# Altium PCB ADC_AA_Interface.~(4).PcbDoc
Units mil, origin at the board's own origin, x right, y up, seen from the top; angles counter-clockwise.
Board outline 2600 x 10000 mil, 6 copper layers (Top Layer, InternalPlane1, MidLayer1, InternalPlane2, InternalPlane3, Bottom Layer); 10 components, 66 nets, 277 pads, 10 vias.
Unrouted connection lines stored in the file: 1.
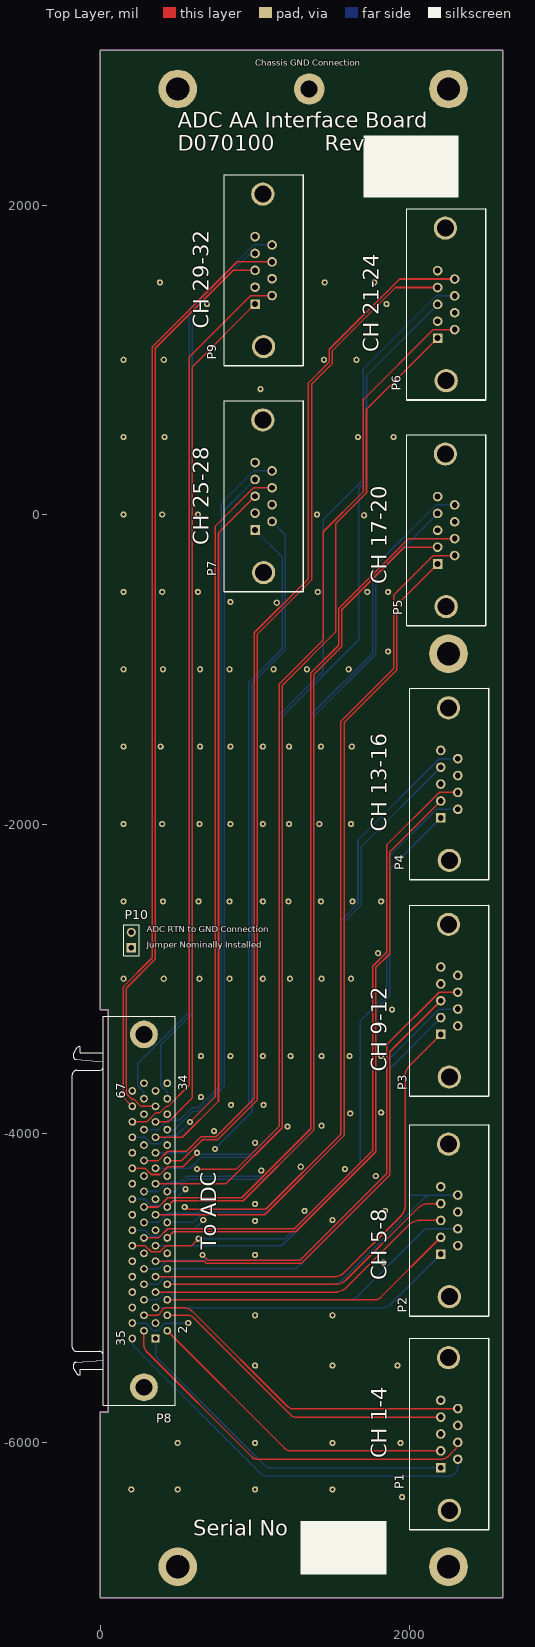
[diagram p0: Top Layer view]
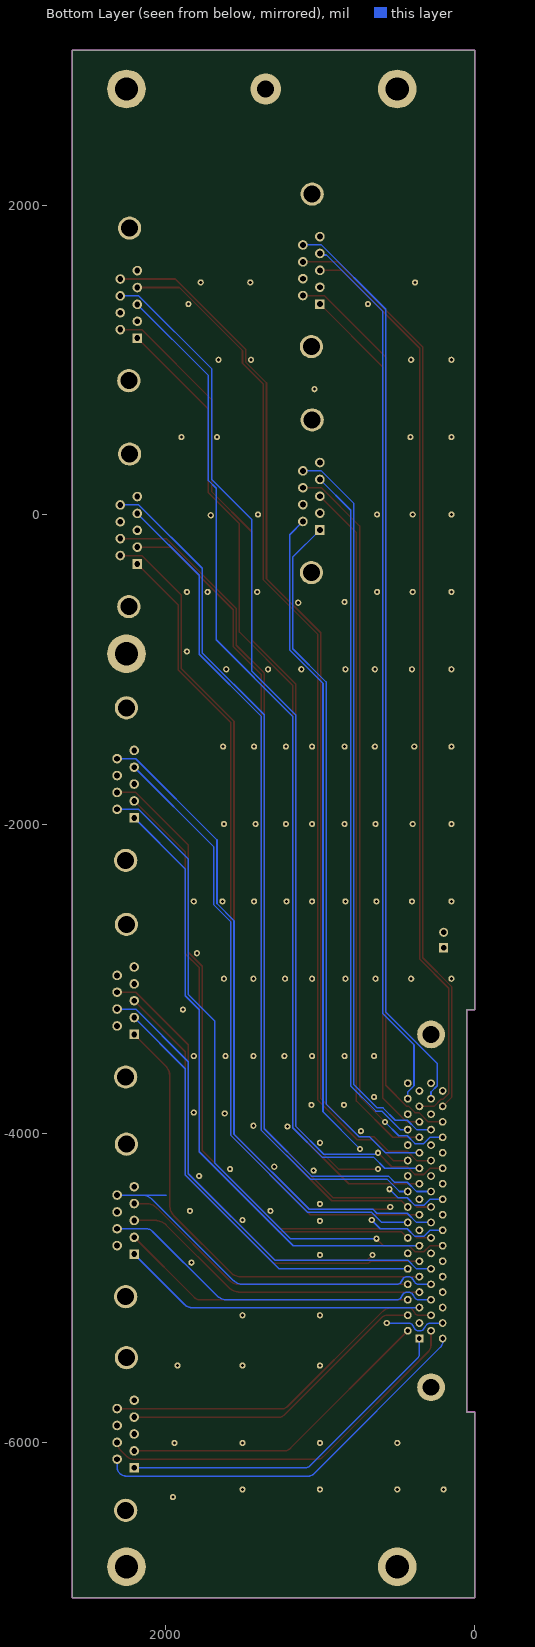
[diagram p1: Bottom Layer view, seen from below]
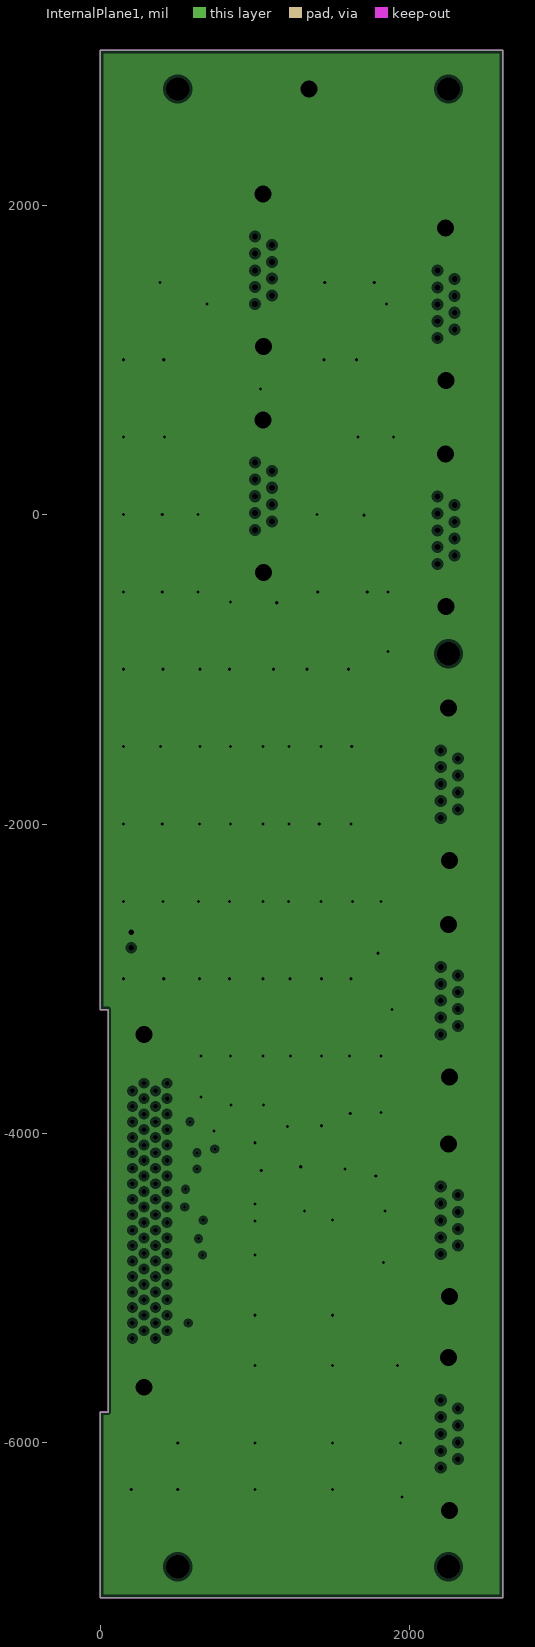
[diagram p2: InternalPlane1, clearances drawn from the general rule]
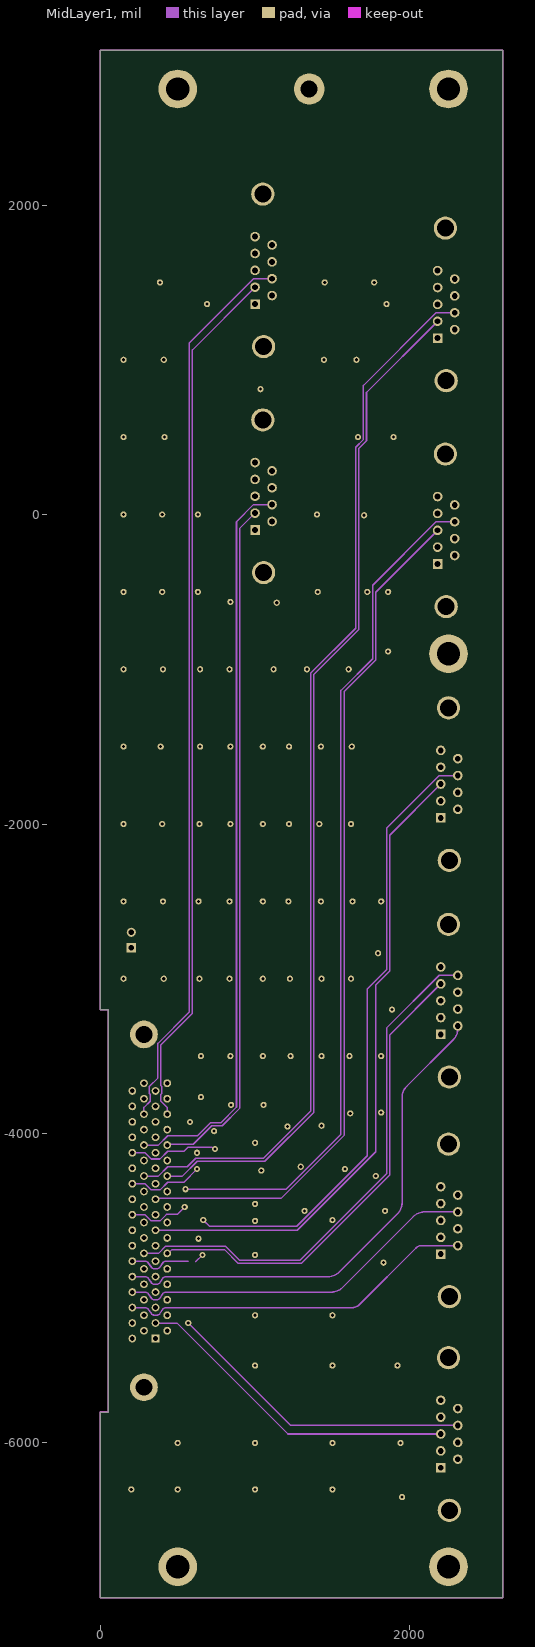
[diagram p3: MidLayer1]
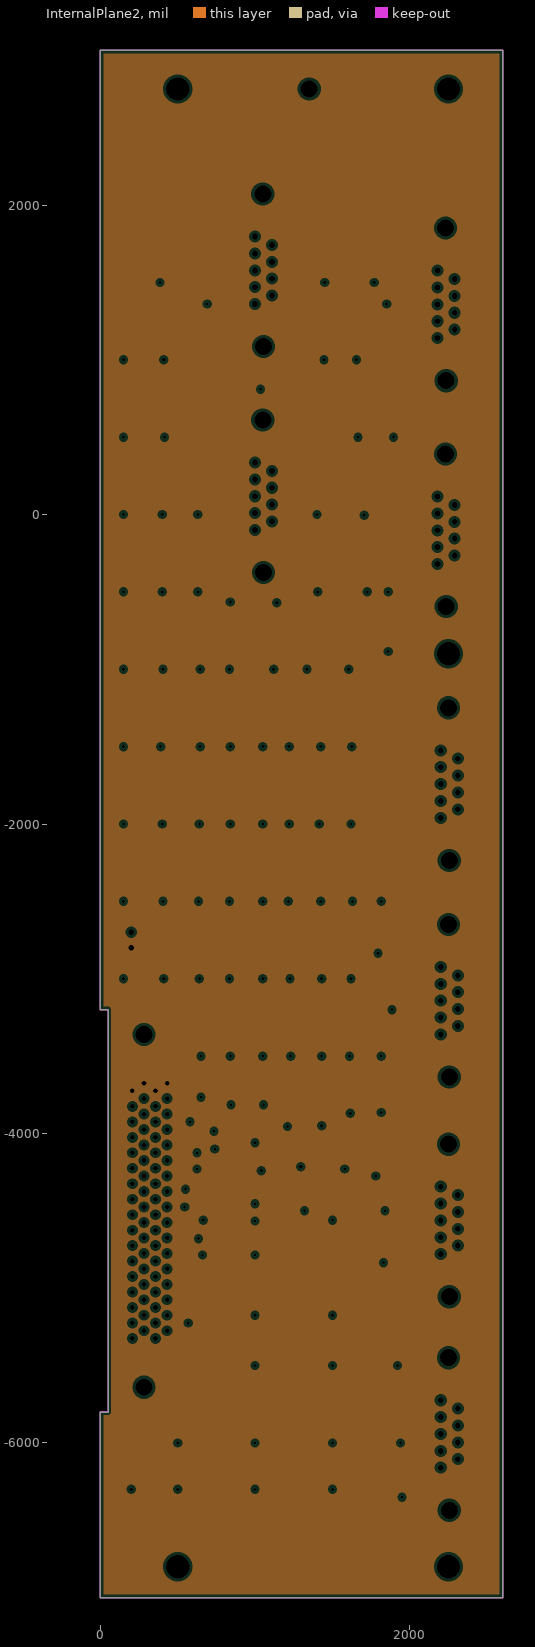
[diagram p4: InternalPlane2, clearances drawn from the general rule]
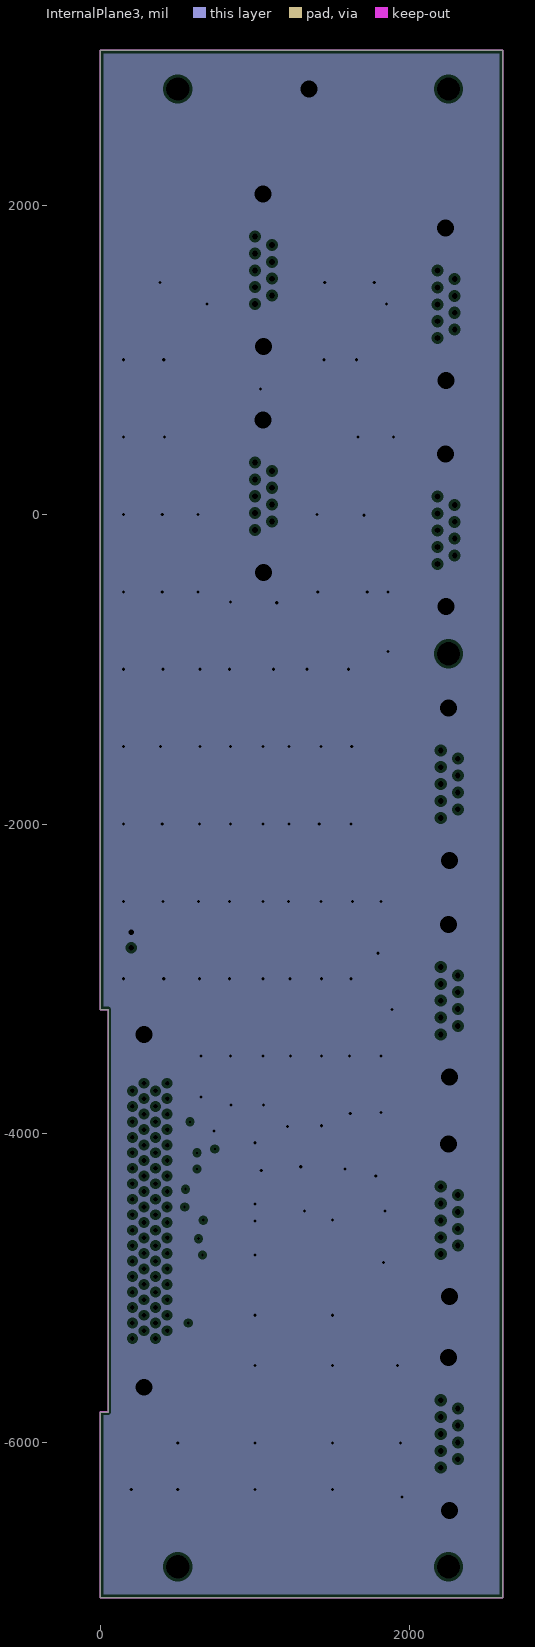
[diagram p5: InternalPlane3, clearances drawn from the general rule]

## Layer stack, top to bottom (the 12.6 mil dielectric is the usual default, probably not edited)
Top Solder: solder mask 0.4, Solder Resist, Dk 3.5
Top Layer: signal copper 1.4
Dielectric1: core 12.6, FR-4, Dk 4.8
InternalPlane1: plane copper 1.4, net GND
Dielectric3: prepreg 12.6, FR-4, Dk 4.8
MidLayer1: signal copper 1.4
Dielectric2: core 12.6, FR-4, Dk 4.8
InternalPlane2: plane copper 1.4, net RTN
Dielectric4: prepreg 12.6, FR-4, Dk 4.8
InternalPlane3: plane copper 1.4, net GND
Dielectric5: core 12.6, FR-4, Dk 4.8
Bottom Layer: signal copper 1.4
Bottom Solder: solder mask 0.4, Solder Resist, Dk 3.5

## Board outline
0,-7000 0,-5800 50,-5800 50,-3200 0,-3200 0,3000 2600,3000 2600,-7000

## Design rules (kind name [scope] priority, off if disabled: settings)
Clearance [All] p1: gap=10 ignorepadtopadclearanceinfootprint=FALSE except(0: Arc-Hole Track-Hole SMDPad-Hole THPad-Hole Via-Hole Fill-Hole Poly-Hole Region-Hole Text-Hole)
FabricationTestPointUsage TestPointUsage [All] p1: valid=0 allowmultiple=FALSE
FabricationTestpoint Testpoint [All] p1: side=3 testpointundercomponent=TRUE minsize=40 maxsize=100 preferedsize=60 minholesize=0 maxholesize=40 preferedholesize=32 testpointgrid=1 allowsidetop=TRUE allowsidebottom=TRUE usegrid=TRUE gridtolerance=0.01
HoleSize [All] p1: absolutevalues=TRUE maxlimit=200 minlimit=1 maxpercent=80.000 minpercent=20.000
PlaneClearance [All] p1: clearance=20
PlaneConnect [All] p1: planeconnectstyle=Relief reliefexpansion=20 reliefentries=4 reliefconductorwidth=10 reliefairgap=10
PolygonConnect [All] p1: connectstyle=Relief reliefconductorwidth=10 reliefentries=4 polygonreliefangle="90 Angle" airgapwidth=10
RoutingVias [All] p1: holewidth=20 width=40 viastyle="Through Hole" minholewidth=20 minwidth=40 maxholewidth=28 maxwidth=50
SolderMaskExpansion [All] p1: expansion=4
Width [All] p1: maxlimit=100 minlimit=10 preferedwidth=10
25 further rules are at their usual default settings.

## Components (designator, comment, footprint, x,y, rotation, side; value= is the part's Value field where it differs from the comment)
P1 "5747871-8" DB9/M 2200,-6160 r270 top
P2 "5747871-8" DB9/M 2200,-4780 r270 top
P3 "5747871-8" DB9/M 2200,-3360 r270 top
P4 "5747871-8" DB9/M 2200,-1960 r270 top
P5 "5747871-8" DB9/M 2180,-320 r270 top
P6 "5747871-8" DB9/M 2180,1140 r270 top
P7 "5747871-8" DB9/M 1000,-100 r270 top
P8 "787082-7" 787082-7 20,-4500 r90 top
P9 "5747871-8" DB9/M 1000,1360 r270 top
P10 "Header 2" HDR1X2 200,-2800 r90 top

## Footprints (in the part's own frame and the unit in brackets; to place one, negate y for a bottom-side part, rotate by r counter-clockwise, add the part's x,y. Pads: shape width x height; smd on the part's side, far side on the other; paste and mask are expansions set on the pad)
787082-7 [mm] "Connector; D Subminiature 050 Series; 68 Position; Right Angle"
  rect 1.27x1.27 hole 0.762: 1(-20.955,-8.555)
  round 1.27 hole 0.762: 2(-19.685,-10.46) 3(-18.415,-8.555) 4(-17.145,-10.46) 5(-15.875,-8.555) 6(-14.605,-10.46) 7(-13.335,-8.555) 8(-12.065,-10.46) 9(-10.795,-8.555) 10(-9.525,-10.46) 11(-8.255,-8.555) 12(-6.985,-10.46) 13(-5.715,-8.555) 14(-4.445,-10.46) 15(-3.175,-8.555) 16(-1.905,-10.46) 17(-0.635,-8.555) 18(0.635,-10.46) 19(1.905,-8.555) 20(3.175,-10.46) 21(4.445,-8.555) 22(5.715,-10.46) 23(6.985,-8.555) 24(8.255,-10.46) 25(9.525,-8.555) 26(10.795,-10.46) 27(12.065,-8.555) 28(13.335,-10.46) 29(14.605,-8.555) 30(15.875,-10.46) 31(17.145,-8.555) 32(18.415,-10.46) 33(19.685,-8.555) 34(20.955,-10.46) 35(-20.955,-4.745) 36(-19.685,-6.65) 37(-18.415,-4.745) 38(-17.145,-6.65) 39(-15.875,-4.745) 40(-14.605,-6.65) 41(-13.335,-4.745) 42(-12.065,-6.65) 43(-10.795,-4.745) 44(-9.525,-6.65) 45(-8.255,-4.745) 46(-6.985,-6.65) 47(-5.715,-4.745) 48(-4.445,-6.65) 49(-3.175,-4.745) 50(-1.905,-6.65) 51(-0.635,-4.745) 52(0.635,-6.65) 53(1.905,-4.745) 54(3.175,-6.65) 55(4.445,-4.745) 56(5.715,-6.65) 57(6.985,-4.745) 58(8.255,-6.65) 59(9.525,-4.745) 60(10.795,-6.65) 61(12.065,-4.745) 62(13.335,-6.65) 63(14.605,-4.745) 64(15.875,-6.65) 65(17.145,-4.745) 66(18.415,-6.65) 67(19.685,-4.745) 68(20.955,-6.65)
  round 4.55 hole 2.77: 69(-28.955,-6.65) 70(28.955,-6.65)
  silkscreen extent -31.95,-11.76 31.95,5.11
DB9/M [mil]
  round 150 hole 110: 0(-711,50) 0(275,55)
  rect 62x62 hole 38: 1(0,0)
  round 62 hole 38: 2(-109,0) 3(-218,0) 4(-327,0) 5(-436,0) 6(-55,110) 7(-164,110) 8(-273,110) 9(-382,110)
  silkscreen extent -836,-200 400,310
HDR1X2 [mm] "Connector; Header; 2 Position"
  rect 1.5x1.5 hole 0.9: 1(0,0)
  round 1.5 hole 0.9: 2(2.54,0)
  silkscreen extent -1.27,-1.27 3.81,1.27

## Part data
P1 P2 P3 P4 P5 P6 P7 P9: library part 788754-1, "Plug Assembly, Size 1, 9 Position, Right Angle, 8.08mm Series, Amplimite"
P8: library part "PE50E-080 Connector", "3M Pak 50 plug connector"
P10: "Header, 2-Pin"

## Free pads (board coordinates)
  round 40 hole 20: 0(500,-6000) 1(1000,-6000) 2(1500,-6000) 3(1940,-6000) 4(1000,-5500) 5(1500,-5500) 6(1920,-5500) 9(1840,-4500) 10(1000,-5175) 11(1500,-5175) 12(1830,-4835) 13(1000,-4785) 14(1500,-4560) 15(1780,-4275) 16(1815,-3865) 17(1815,-3500) 18(1885,-3200) 19(1000,-4565) 20(1320,-4500) 21(1580,-4230) 22(1615,-3870) 23(1610,-3500) 24(1620,-3000) 25(1795,-2835) 26(1000,-4455) 27(1295,-4215) 28(1040,-4240) 29(1430,-3950) 30(1430,-3500) 31(1430,-3000) 32(1230,-3500) 33(1225,-3000) 34(1210,-3955) 35(1000,-4060) 36(735,-3985) 37(845,-3815) 38(840,-3500) 39(835,-3000) 40(835,-2500) 41(405,-2500) 42(635,-2500) 43(410,-3000) 44(640,-3000) 45(1050,-2500) 46(1215,-2500) 47(1425,-2500) 48(1630,-2500) 49(1815,-2500) 50(650,-3500) 51(650,-3765) 52(1055,-3815) 53(1050,-3500) 54(1050,-3000) 55(400,-2000) 56(640,-2000) 57(840,-2000) 58(1050,-2000) 59(1220,-2000) 60(1415,-2000) 61(1620,-2000) 62(1625,-1500) 63(1425,-1500) 64(1220,-1500) 65(1050,-1500) 66(840,-1500) 67(645,-1500) 68(390,-1500) 69(405,-1000) 70(645,-1000) 71(835,-1000) 72(1120,-1000) 73(1335,-1000) 74(1605,-1000) 75(1860,-885) 76(150,1000) 76(1860,-500) 77(150,500) 77(1725,-500) 78(150,0) 78(400,-500) 79(150,-500) 79(630,-500) 80(150,-1000) 80(840,-565) 81(150,-1500) 81(1140,-570) 82(150,-2000) 82(1405,-500) 83(150,-2500) 83(400,0) 84(150,-3000) 84(630,0) 85(200,-6300) 85(1400,0) 86(500,-6300) 86(1705,-5) 87(1000,-6300) 87(1665,500) 88(415,500) 88(1500,-6300) 89(410,1000) 89(1950,-6350) 90(1035,810) 91(1445,1000) 92(1655,1000) 93(1895,500) 94(1450,1500) 95(1770,1500) 96(385,1500) 97(690,1360) 98(1850,1360)
  round 200 hole 110: 0(1350,2750)
  round 250 hole 150: 0(2250,-6800) 1(2250,2750) 2(500,2750) 3(500,-6800) 4(2250,-900)

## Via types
v1: diameter 40, hole 20, Top Layer to Bottom Layer, 10 vias

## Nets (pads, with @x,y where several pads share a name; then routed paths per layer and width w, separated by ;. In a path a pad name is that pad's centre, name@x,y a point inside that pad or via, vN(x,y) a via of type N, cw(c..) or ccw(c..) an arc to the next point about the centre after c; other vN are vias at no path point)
GND: P1.0 P2.0 P3.0 P4.0 P5.0 P6.0 P7.0 P8.69 P8.70 P9.0 P10.2 pad.0@500,-6000 pad.0@1350,2750 pad.1@1000,-6000 pad.2@1500,-6000 pad.3@1940,-6000 pad.4@1000,-5500 pad.5 pad.6 pad.9 pad.10 pad.11 pad.12 pad.13 pad.14 pad.15 pad.16 pad.17 pad.18 pad.19 pad.20 pad.21 pad.22 pad.23 pad.24 pad.25 pad.26 pad.27 pad.28 pad.29 pad.30 pad.31 pad.32 pad.33 pad.34 pad.35 pad.36 pad.37 pad.38 pad.39 pad.40 pad.41 pad.42 pad.43 pad.44 pad.45 pad.46 pad.47 pad.48 pad.49 pad.50 pad.51 pad.52 pad.53 pad.54 pad.55 pad.56 pad.57 pad.58 pad.59 pad.60 pad.61 pad.62 pad.63 pad.64 pad.65 pad.66 pad.67 pad.68 pad.69 pad.70 pad.71 pad.72 pad.73 pad.74 pad.75 pad.76 pad.77 pad.78 pad.79 pad.80 pad.81 pad.82 pad.83 pad.84 pad.85 pad.86 pad.87 pad.88 pad.89 pad.90 pad.91 pad.92 pad.93 pad.94 pad.95 pad.96 pad.97 pad.98
OUTPUTN1: P1.6 P8.35 | length 2576
  Bottom Layer w10: P8.35 206.81,-5348.16 ccw(c251.84,-5348.16) 220,-5380 1040,-6200 ccw(c1073.8,-6166.2) 1073.8,-6214 2251.92,-6214 ccw(c2251.92,-6155.87) 2293.03,-6196.97 ccw(c2251.96,-6155.96) 2310,-6155.96 P1.6
OUTPUTN2: P1.7 P8.36 | length 2523.7
  Top Layer w10: P8.36 281.81,-5370 ccw(c334.47,-5370) 297.23,-5407.23 ; 300,-5410 297.23,-5407.23 ; 1020,-6105 1016.21,-6105 ; P1.7@2310,-6020 P1.7 cw(c2239.99,-5996) 2289.49,-6045.51 2251.21,-6083.79 cw(c2200,-6032.57) 2200,-6105 1016.21,-6105 ; 297.23,-5407.23 980.03,-6090.03 ccw(c1016.21,-6053.79) 1016.21,-6105
OUTPUTN3: P1.8 P8.37 | length 2419.6
  MidLayer1 w10: v1(568.12,-5225) 1230.12,-5887 P1.8
  Bottom Layer w10: P8.37 280,-5225 ; 281.81,-5225 cw(c281.81,-5275) 307.3,-5231.99 ; 406.18,-5232.07 382.54,-5267.87 cw(c356.81,-5225) 331.08,-5267.87 307.44,-5232.07 ; 406.32,-5231.99 cw(c431.81,-5275) 431.81,-5225 v1(568.12,-5225) ; 307.3,-5231.99 cw(c281.81,-5275) 307.44,-5232.07 ; 307.3,-5231.99 cw(c356.81,-5225) 307.28,-5231.82 307.44,-5232.07
OUTPUTN4: P1.9 P8.38 | length 2322.5
  Top Layer w10: P8.38 355,-5175 ; 356.81,-5175 ccw(c356.81,-5125) 382.3,-5168.01 ; 382.44,-5167.93 406.08,-5132.13 cw(c431.81,-5175) 431.81,-5125 528.58,-5125 cw(c528.58,-5225) 599.29,-5154.29 1210.98,-5765.98 ccw(c1240,-5736.96) 1240,-5778 ; 1230,-5778 1240,-5778 ; P1.9 1240,-5778
OUTPUTN5: P2.6 P8.39 | length 2310.1
  MidLayer1 w10: P8.39 280,-5125 ; 281.81,-5125 cw(c281.81,-5175) 307.3,-5131.99 ; 406.18,-5132.07 382.54,-5167.87 cw(c356.81,-5125) 356.81,-5175 cw(c356.81,-5125) 331.08,-5167.87 307.44,-5132.07 ; 406.32,-5131.99 cw(c431.81,-5175) 431.81,-5125 1630,-5125 ccw(c1630,-5064.64) 1672.68,-5107.32 2040.03,-4739.97 cw(c2076.21,-4776.21) 2076.21,-4725 ; 2080,-4725 2076.21,-4725 ; P2.6 2076.21,-4725 ; 307.3,-5131.99 cw(c356.81,-5125) 307.28,-5131.82 307.44,-5132.07 ; 307.3,-5131.99 cw(c281.81,-5175) 307.44,-5132.07
OUTPUTN6: P2.7 P8.40 | length 2254
  Bottom Layer w10: P8.40 355,-5075 ; 356.81,-5075 ccw(c356.81,-5025) 382.3,-5068.01 ; 481.18,-5067.93 457.54,-5032.13 ccw(c431.81,-5075) 406.08,-5032.13 382.44,-5067.93 ; 481.32,-5068.01 ccw(c506.81,-5025) 506.81,-5075 1598.08,-5075 ccw(c1598.08,-4975) 1668.79,-5045.71 2083.29,-4631.2 cw(c2120,-4667.91) 2120,-4616 P2.7 ; 382.3,-5068.01 ccw(c431.81,-5075) 382.28,-5068.18 382.44,-5067.93 ; 382.3,-5068.01 ccw(c356.81,-5025) 382.44,-5067.93
OUTPUTN7: P2.8 P8.41 | length 2351.3
  MidLayer1 w10: P8.41 280,-5025 ; 281.81,-5025 cw(c281.81,-5075) 307.3,-5031.99 ; 406.18,-5032.07 382.54,-5067.87 cw(c356.81,-5025) 356.81,-5075 cw(c356.81,-5025) 331.08,-5067.87 307.44,-5032.07 ; 406.32,-5031.99 cw(c431.81,-5075) 431.81,-5025 1364.5,-5025 1493.58,-5025 ccw(c1493.58,-4925) 1564.29,-4995.71 2023.71,-4536.29 cw(c2094.42,-4607) 2094.42,-4507 P2.8 ; 307.3,-5031.99 cw(c356.81,-5025) 307.28,-5031.82 307.44,-5032.07 ; 307.3,-5031.99 cw(c281.81,-5075) 307.44,-5032.07
OUTPUTN8: P2.9 P8.42 | length 2462.7
  Bottom Layer w10: P8.42 355,-4975 ; 356.81,-4975 ccw(c356.81,-4925) 382.3,-4968.01 ; 481.18,-4967.93 457.54,-4932.13 ccw(c431.81,-4975) 406.08,-4932.13 382.44,-4967.93 ; 481.32,-4968.01 ccw(c506.81,-4925) 506.81,-4975 1493.58,-4975 ccw(c1493.58,-4875) 1564.29,-4945.71 2082.71,-4427.29 cw(c2153.42,-4498) 2153.42,-4398 ; 1991.5,-4398 2153.42,-4398 ; P2.9 2153.42,-4398 ; 382.3,-4968.01 ccw(c431.81,-4975) 382.28,-4968.18 382.44,-4967.93 ; 382.3,-4968.01 ccw(c356.81,-4925) 382.44,-4967.93
OUTPUTN9: P3.6 P8.43 | length 3282.4
  MidLayer1 w10: P8.43 280,-4925 ; 281.81,-4925 cw(c281.81,-4975) 307.3,-4931.99 ; 406.18,-4932.07 382.54,-4967.87 cw(c356.81,-4925) 356.81,-4975 cw(c356.81,-4925) 331.08,-4967.87 307.44,-4932.07 ; 406.32,-4931.99 cw(c431.81,-4975) 431.81,-4925 1473.58,-4925 ccw(c1473.58,-4825) 1544.29,-4895.71 1920.71,-4519.29 ccw(c1850,-4448.58) 1950,-4448.58 1950,-3766.42 cw(c2050,-3766.42) 1979.29,-3695.71 2280.71,-3394.29 ccw(c2210,-3323.58) 2310,-3323.58 P3.6 ; 307.3,-4931.99 cw(c356.81,-4925) 307.28,-4931.82 307.44,-4932.07 ; 307.3,-4931.99 cw(c281.81,-4975) 307.44,-4932.07
OUTPUTN10: P3.7 P8.44 | length 3147.5
  Bottom Layer w10: P8.44 375.24,-4875 430.24,-4820 1289.5,-4820 1850,-4259.5 1850,-3535.95 2189.95,-3196 P3.7
OUTPUTN11: P3.8 P8.45 | length 3334.1
  Top Layer w10: v1(660,-4785) 695,-4820 1289.5,-4820 1850,-4259.5 1850,-3426.95 2189.95,-3087 P3.8
  MidLayer1 w10: P8.45 280,-4825 ; 281.81,-4825 cw(c281.81,-4875) 307.3,-4831.99 ; 406.18,-4832.07 382.54,-4867.87 cw(c356.81,-4825) 356.81,-4875 cw(c356.81,-4825) 331.08,-4867.87 307.44,-4832.07 ; 406.32,-4831.99 cw(c431.81,-4875) 431.81,-4825 568.12,-4825 ; 617.13,-4827.87 v1(660,-4785) ; 307.3,-4831.99 cw(c356.81,-4825) 307.28,-4831.82 307.44,-4832.07 ; 307.3,-4831.99 cw(c281.81,-4875) 307.44,-4832.07
OUTPUTN12: P3.9 P8.46 | length 3398.6
  MidLayer1 w10: P8.46 375.24,-4775 420.24,-4730 809.87,-4730 899.87,-4820 1289.5,-4820 1850,-4259.5 1850,-3317.95 2189.95,-2978 P3.9
OUTPUTN13: P4.6 P8.47 | length 4354.6
  Top Layer w10: P8.47 288.38,-4725 328.38,-4765 385.24,-4765 424.87,-4725.37 589.63,-4725.37 v1(635,-4680)
  Bottom Layer w10: v1(635,-4680) 1189.5,-4680 1679.01,-4190.49 1679.01,-3272.7 1850,-3101.72 1850,-2226.79 2171.79,-1905 P4.6
OUTPUTN14: P4.7 P8.48 | length 4324.1
  Top Layer w10: P8.48 375.24,-4675 435.24,-4615 1254.5,-4615 1760,-4109.5 1760,-2919.5 1850,-2829.5 1850,-2135.95 2189.95,-1796 P4.7
OUTPUTN15: P4.8 P8.49 | length 4553.6
  MidLayer1 w10: v1(665,-4560) 705,-4600 1269.5,-4600 1725.22,-4144.28 1725.22,-3066.49 1850,-2941.72 1850,-2026.95 2189.95,-1687 P4.8
  Bottom Layer w10: P8.49 288.38,-4625 328.38,-4665 385.24,-4665 434.87,-4615.37 609.63,-4615.37 v1(665,-4560)
OUTPUTN16: P4.9 P8.50 | length 4319.1
  Bottom Layer w10: P8.50 375.24,-4575 435.24,-4515 632.22,-4515 657.22,-4490 1069.5,-4490 1555,-4004.5 1555,-2624.5 1665,-2514.5 1665,-2102.95 2189.95,-1578 P4.9
OUTPUTN17: P5.6 P8.51 | length 5734.3
  Top Layer w10: v1(545,-4475) 553.12,-4475 568.12,-4490 1069.5,-4490 1555,-4004.5 1555,-1336.72 1895,-996.72 1895,-521.79 2151.79,-265 P5.6
  MidLayer1 w10: P8.51 288.38,-4525 328.38,-4565 385.24,-4565 427.37,-4522.87 497.13,-4522.87 v1(545,-4475)
OUTPUTN18: P5.7 P8.52 | length 5661.3
  Top Layer w10: P8.52 375.24,-4475 435.24,-4415 914.5,-4415 1360,-3969.5 1360,-1024.5 1540,-844.5 1540,-607.22 1991.22,-156 P5.7
OUTPUTN19: P5.8 P8.53 | length 5887.8
  MidLayer1 w10: v1(550,-4360) 1199.5,-4360 1555,-4004.5 1555,-1136.72 1760,-931.72 1760,-456.95 2169.95,-47 P5.8
  Bottom Layer w10: P8.53 288.38,-4425 328.38,-4465 385.24,-4465 434.87,-4415.37 494.63,-4415.37 v1(550,-4360)
OUTPUTN20: P5.9 P8.54 | length 5733.2
  Bottom Layer w10: P8.54 375.24,-4375 435.24,-4315 517.22,-4315 557.22,-4275 1054.5,-4275 1360,-3969.5 1360,-1294.5 1760,-894.5 1760,-347.95 2169.95,62 P5.9
OUTPUTN21: P6.6 P8.55 | length 6835.4
  Top Layer w10: v1(625,-4230) 879.5,-4230 1155,-3954.5 1155,-1096.72 1440,-811.72 1440,-111.72 1700,148.28 1700,743.21 2151.79,1195 P6.6
  MidLayer1 w10: P8.55 288.38,-4325 328.38,-4365 385.24,-4365 435.24,-4315 540,-4315 v1(625,-4230)
OUTPUTN22: P6.7 P8.56 | length 6866.4
  MidLayer1 w10: P8.56 375.24,-4275 435.24,-4215 562.22,-4215 617.22,-4160 1054.5,-4160 1360,-3854.5 1360,-1024.5 1650,-734.5 1650,435.5 1700,485.5 1700,834.05 2169.95,1304 P6.7
OUTPUTN23: P6.8 P8.57 | length 7009.6
  Top Layer w10: P8.57 288.38,-4225 328.38,-4265 385.24,-4265 435.24,-4215 535,-4215 v1(625,-4125)
  Bottom Layer w10: v1(625,-4125) 633.12,-4125 643.12,-4135 974.5,-4135 1155,-3954.5 1155,-1296.72 1440,-1011.72 1440,-31.72 1700,228.28 1700,943.05 2169.95,1413 P6.8
OUTPUTN24: P6.9 P8.58 | length 6920.4
  Top Layer w10: P8.58 375.24,-4175 435.24,-4115 557.22,-4115 652.22,-4020 749.5,-4020 995,-3774.5 995,-764.5 1345,-414.5 1345,850.5 1480,985.5 1480,1067.78 1934.22,1522 P6.9
OUTPUTN25: P7.6 P8.59 | length 4863.6
  MidLayer1 w10: P8.59 288.38,-4125 328.38,-4165 385.24,-4165 435.24,-4115 540,-4115 565,-4090 721.88,-4090 731.88,-4100 v1(740,-4100)
  Bottom Layer w10: v1(740,-4100) 980,-3860 980,-1090.5 1195,-875.5 1195,-130 P7.6
OUTPUTN26: P7.7 P8.60 | length 4759
  MidLayer1 w10: P8.60 375.24,-4075 435.24,-4015 627.22,-4015 712.22,-3930 779.5,-3930 880,-3829.5 880,-45.95 989.95,64 P7.7
OUTPUTN27: P7.8 P8.61 | length 4835.6
  Top Layer w10: v1(580,-3925) 743.6,-3761.4 743.6,-73.35 989.95,173 P7.8
  Bottom Layer w10: P8.61 288.38,-4025 328.38,-4065 385.24,-4065 435.24,-4015 490,-4015 v1(580,-3925)
OUTPUTN28: P7.9 P8.62 | length 4792
  Bottom Layer w10: P8.62 375.24,-3975 435.24,-3915 512.22,-3915 592.22,-3835 629.5,-3835 780,-3684.5 780,72.05 989.95,282 P7.9
OUTPUTN29: P8.63 P9.6 | length 5872.1
  Top Layer w10: P8.63 300.24,-3925 360.24,-3865 385.24,-3865 424.88,-3825.36 438.02,-3825.36 575,-3688.38 575,1018.21 971.79,1415 P9.6
OUTPUTN30: P8.64 P9.7 | length 5816.5
  MidLayer1 w10: P8.64 281.81,-3831.57 321.81,-3791.57 321.81,-3746.57 316.81,-3741.57 316.81,-3696.57 371.81,-3641.57 371.81,-3417.92 575,-3214.73 575,1109.05 989.95,1524 P9.7
OUTPUTN31: P8.65 P9.8 | length 6013.5
  Top Layer w10: P8.65 146.81,-3765 146.81,-3052.69 335,-2864.5 335,1082.78 885.22,1633 P9.8
OUTPUTN32: P8.66 P9.9 | length 5963.5
  Bottom Layer w10: P8.66 281.81,-3731.57 241.81,-3691.57 241.81,-3547.92 575,-3214.73 575,1327.05 989.95,1742 P9.9
OUTPUTP1: P1.1 P8.1 | length 2253.2
  Bottom Layer w10: P8.1 356.81,-5420 356.81,-5421.44 ccw(c401.84,-5421.44) 370,-5453.28 1066.72,-6150 1067.32,-6150.61 ; 1067.33,-6150.61 ccw(c1090,-6127.93) 1090,-6160 P1.1
OUTPUTP2: P1.2 P8.2 | length 2087.3
  Top Layer w10: P8.2 1190,-6033.19 1192.12,-6035.31 ccw(c1230,-5997.43) 1230,-6051 P1.2
OUTPUTP3: P1.3 P8.3 | length 2140.2
  MidLayer1 w10: P8.3 495,-5225 1212,-5942 P1.3
OUTPUTP4: P1.4 P8.4 | length 2037.2
  Top Layer w10: P8.4 567.62,-5175 cw(c567.62,-5221.51) 600.51,-5188.62 1234.19,-5822.31 ccw(c1260,-5796.5) 1260,-5833 P1.4
OUTPUTP5: P2.1 P8.5 | length 1983.5
  Bottom Layer w10: P8.5 645,-5125 1830,-5125 ccw(c1830,-5064.64) 1872.65,-5107.35 ; 1872.68,-5107.32 1880,-5100 P2.1
OUTPUTP6: P2.2 P8.6 | length 1933.3
  Top Layer w10: P8.6 1775,-5075 ccw(c1775,-5024.3) 1810.85,-5060.15 P2.2
OUTPUTP7: P2.3 P8.7 | length 2026.4
  Top Layer w10: P8.7 1518.58,-5025 ccw(c1518.58,-4925) 1589.29,-4995.71 1993.71,-4591.29 cw(c2064.42,-4662) 2064.42,-4562 P2.3
OUTPUTP8: P2.4 P8.8 | length 1975.8
  Top Layer w10: P8.8 1518.58,-4975 ccw(c1518.58,-4875) 1589.29,-4945.71 2052.71,-4482.29 cw(c2123.42,-4553) 2123.42,-4453 P2.4
OUTPUTP9: P3.1 P8.9 | length 3015.3
  Top Layer w10: P8.9 1515.65,-4925 ccw(c1515.65,-4842.07) 1574.29,-4900.71 1940.71,-4534.29 ccw(c1870,-4463.58) 1970,-4463.58 1970,-3631.42 cw(c2070,-3631.42) 1999.29,-3560.71 P3.1
OUTPUTP10: P3.2 P8.10 | length 2843.2
  Bottom Layer w10: P8.10 1262.78,-4875 1870,-4267.78 1870,-3581 P3.2
OUTPUTP11: P3.3 P8.11 | length 3018.9
  Top Layer w10: P8.11 671.72,-4825 686.72,-4840 1297.78,-4840 1870,-4267.78 1870,-3472 P3.3
OUTPUTP12: P3.4 P8.12 | length 3094.3
  MidLayer1 w10: P8.12 438.38,-4775 463.38,-4750 801.59,-4750 891.59,-4840 1297.78,-4840 1870,-4267.78 1870,-3363 P3.4
OUTPUTP13: P4.1 P8.13 | length 4006.5
  Bottom Layer w10: P8.13 1172.78,-4725 1780,-4117.78 1780,-3200 1870,-3110 1870,-2290 P4.1
OUTPUTP14: P4.2 P8.14 | length 4019.7
  Top Layer w10: P8.14 471.81,-4635 1262.78,-4635 1780,-4117.78 1780,-2927.78 1870,-2837.78 1870,-2181 P4.2
OUTPUTP15: P4.3 P8.15 | length 4183
  MidLayer1 w10: P8.15 1272.78,-4625 1780,-4117.78 1780,-3040 1870,-2950 1870,-2072 P4.3
OUTPUTP16: P4.4 P8.16 | length 4014.7
  Bottom Layer w10: P8.16 600.5,-4575 665.5,-4510 1077.78,-4510 1575,-4012.78 1575,-2632.78 1685,-2522.78 1685,-2148 P4.4
OUTPUTP17: P5.1 P8.17 | length 5373.7
  Top Layer w10: P8.17 1062.78,-4525 1575,-4012.78 1575,-1345 1915,-1005 1915,-585 P5.1
OUTPUTP18: P5.2 P8.18 | length 5378.5
  Top Layer w10: P8.18 471.81,-4435 922.78,-4435 1380,-3977.78 1380,-1032.78 1560,-852.78 1560,-615.5 1964.5,-211 P5.2
OUTPUTP19: P5.3 P8.19 | length 5550.3
  MidLayer1 w10: P8.19 361.81,-4420 1167.78,-4420 1575,-4012.78 1575,-1145 1780,-940 1780,-502 P5.3
OUTPUTP20: P5.4 P8.20 | length 5428.9
  Bottom Layer w10: P8.20 485.5,-4375 565.5,-4295 1062.78,-4295 1380,-3977.78 1380,-1302.78 1780,-902.78 1780,-393 P5.4
OUTPUTP21: P6.1 P8.21 | length 6487.3
  Top Layer w10: P8.21 812.78,-4325 1175,-3962.78 1175,-1105 1520,-760 1520,-60 1720,140 1720,680 P6.1
OUTPUTP22: P6.2 P8.22 | length 6562.1
  MidLayer1 w10: P8.22 530.5,-4275 625.5,-4180 1062.78,-4180 1380,-3862.78 1380,-1032.78 1670,-742.78 1670,427.22 1720,477.22 1720,789 P6.2
OUTPUTP23: P6.3 P8.23 | length 6663.9
  Bottom Layer w10: P8.23 580.5,-4225 650.5,-4155 982.78,-4155 1175,-3962.78 1175,-1305 1670,-810 1670,170 1720,220 1720,898 P6.3
OUTPUTP24: P6.4 P8.24 | length 6637.6
  Top Layer w10: P8.24 525.5,-4175 660.5,-4040 757.78,-4040 1015,-3782.78 1015,-772.78 1365,-422.78 1365,842.22 1500,977.22 1500,1059.5 1907.5,1467 P6.4
OUTPUTP25: P7.1 P8.25 | length 4604.9
  Bottom Layer w10: P8.25 575.5,-4125 680.5,-4020 749.5,-4020 960,-3809.5 960,-1082.22 1175,-867.22 1175,-275 P7.1
OUTPUTP26: P7.2 P8.26 | length 4454.7
  MidLayer1 w10: P8.26 436.81,-4070 600.5,-4070 720.5,-3950 787.78,-3950 900,-3837.78 900,-91 P7.2
OUTPUTP27: P7.3 P8.27 | length 4510.6
  Top Layer w10: P8.27 529.5,-4025 763.6,-3790.9 763.6,-118.4 P7.3
OUTPUTP28: P7.4 P8.28 | length 4487.7
  Bottom Layer w10: P8.28 480.5,-3975 600.5,-3855 637.78,-3855 800,-3692.78 800,27 P7.4
OUTPUTP29: P8.29 P9.1 | length 5599.2
  Top Layer w10: P8.29 438.38,-3925 595,-3768.38 595,955 P9.1
OUTPUTP30: P8.30 P9.2 | length 5616.6
  MidLayer1 w10: P8.30 431.81,-3831.57 391.81,-3791.57 391.81,-3746.57 396.81,-3741.57 396.81,-3696.57 391.81,-3691.57 391.81,-3426.2 595,-3223.01 595,1064 P9.2
OUTPUTP31: P8.31 P9.3 | length 5972.1
  Top Layer w10: P8.31 263.38,-3825 217.84,-3779.46 204.7,-3779.46 166.81,-3741.57 166.81,-3060.97 355,-2872.78 355,1074.5 858.5,1578 P9.3
OUTPUTP32: P8.32 P9.4 | length 5749.5
  Bottom Layer w10: P8.32 431.81,-3731.57 391.81,-3691.57 391.81,-3426.2 595,-3223.01 595,1314.5 957.55,1677.05 990.05,1677.05 P9.4
RTN: P8.33 P8.34 P8.67 P8.68 P10.1
pads on no net: P1.5 P2.5 P3.5 P4.5 P5.5 P6.5 P7.5 P9.5

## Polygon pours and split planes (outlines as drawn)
GND on InternalPlane1 (split plane): 2579.9,-6979.9 20.1,-6979.9 20.1,-5820.1 50,-5820.1 53.92,-5819.71 57.69,-5818.57 61.17,-5816.71 64.21,-5814.21 66.71,-5811.17 68.57,-5807.69 69.71,-5803.92 70.1,-5800 70.1,-3200 69.71,-3196.08 68.57,-3192.31 66.71,-3188.83 64.21,-3185.79 61.17,-3183.29 57.69,-3181.43 53.92,-3180.29 50,-3179.9 20.1,-3179.9 20.1,2979.9 2579.9,2979.9
RTN on InternalPlane2 (split plane): 2579.9,-6979.9 20.1,-6979.9 20.1,-5820.1 50,-5820.1 53.92,-5819.71 57.69,-5818.57 61.17,-5816.71 64.21,-5814.21 66.71,-5811.17 68.57,-5807.69 69.71,-5803.92 70.1,-5800 70.1,-3200 69.71,-3196.08 68.57,-3192.31 66.71,-3188.83 64.21,-3185.79 61.17,-3183.29 57.69,-3181.43 53.92,-3180.29 50,-3179.9 20.1,-3179.9 20.1,2979.9 2579.9,2979.9
GND on InternalPlane3 (split plane): 2579.9,-6979.9 20.1,-6979.9 20.1,-5820.1 50,-5820.1 53.92,-5819.71 57.69,-5818.57 61.17,-5816.71 64.21,-5814.21 66.71,-5811.17 68.57,-5807.69 69.71,-5803.92 70.1,-5800 70.1,-3200 69.71,-3196.08 68.57,-3192.31 66.71,-3188.83 64.21,-3185.79 61.17,-3183.29 57.69,-3181.43 53.92,-3180.29 50,-3179.9 20.1,-3179.9 20.1,2979.9 2579.9,2979.9

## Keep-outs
Keep-Out Layer:
  the board outline again, w10

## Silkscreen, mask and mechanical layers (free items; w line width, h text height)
Top Overlay:
  rectangle: 1295,-6850 1850,-6505
  rectangle: 1700,2050 2315,2450
  text "Chassis GND Connection" at 1000,2900 h40
  text "ADC AA Interface Board" at 500,2500 h100
  text "D070100" at 500,2350 h100
  text "Rev" at 1450,2350 h100
  text "CH 29-32" at 700,1200 h100 r90
  text "CH 21-24" at 1800,1050 h100 r90
  text "CH 25-28" at 700,-200 h100 r90
  text "CH 17-20" at 1850,-450 h100 r90
  text "CH 13-16" at 1850,-2050 h100 r90
  text "ADC RTN to GND Connection" at 300,-2700 h40
  text "Jumper Nominally Installed" at 300,-2800 h40
  text "CH 9-12" at 1850,-3600 h100 r90
  text "To ADC" at 750,-4750 h100 r90
  text "CH 5-8" at 1850,-4950 h100 r90
  text "CH 1-4" at 1850,-6100 h100 r90
  text "Serial No" at 600,-6600 h100
Mechanical 1:
  lines w10: 0,-7000 0,-5800 50,-5800 50,-4500 50,-3200 0,-3200 0,3000 2600,3000 2600,-7000 0,-7000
